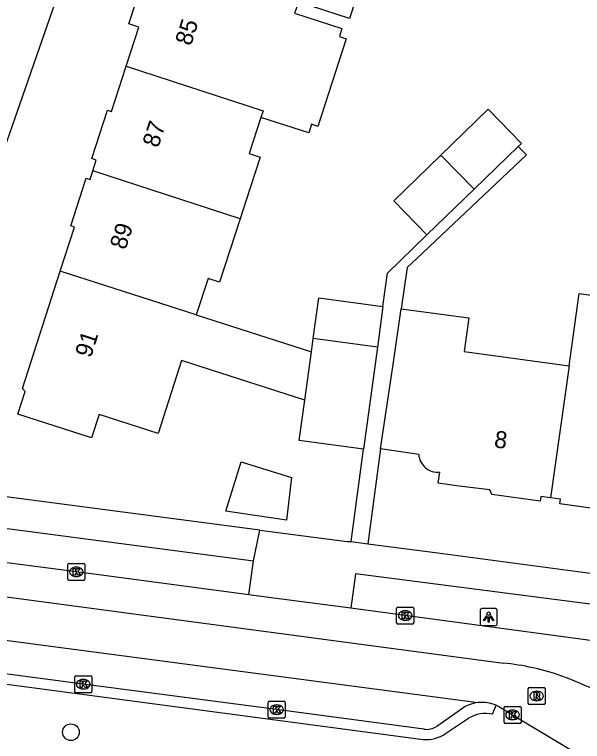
# Model space of a CAD drawing. Extents: x 161402 to 161933, y 381650 to 382313.
# Drawn here: x 161760.54 to 161793.88, y 381673.98 to 381716.7 of the extents above; entities that cross this region are included whole.
import ezdxf

# ---------------------------------------------------------------- set-up
doc = ezdxf.new("R2010")
doc.units = 0
for name, color, linetype in [('IMGEO_Boom', 7, 'Continuous'), ('IMGEO_Kolk', 7, 'Continuous'), ('IMGEO_Lichtpunt', 7, 'Continuous'), ('IMGEO_Pand', 7, 'Continuous'), ('IMGEO_Pand_nummerreeks', 7, 'Continuous'), ('IMGEO_Pand_vergunning_verleend', 7, 'Continuous'), ('IMGEO_Rijbaan_lokaal_gesloten', 7, 'Continuous'), ('IMGEO_Rijbaan_lokaal_open', 7, 'Continuous'), ('IMGEO_Rioolput', 7, 'Continuous'), ('IMGEO_Voetpad_open', 7, 'Continuous')]:
    doc.layers.add(name, color=color, linetype=linetype)

msp = doc.modelspace()

# ---------------------------------------------------------------- linework, layer by layer
at = {"layer": 'IMGEO_Boom'}
msp.add_circle((161763.852, 381674.528), 0.489, dxfattribs=at)
at = {"layer": 'IMGEO_Kolk'}
for p, q in [((161763.669, 381683.525), (161763.669, 381684.377)), ((161763.744, 381684.451), (161764.596, 381684.451)), ((161764.157, 381684.231), (161764.182, 381684.231)), ((161764.67, 381684.377), (161764.67, 381683.525)), ((161764.596, 381683.451), (161763.744, 381683.451)), ((161764.18, 381683.671), (161764.155, 381683.671)), ((161782.973, 381680.957), (161782.973, 381681.809)), ((161783.048, 381681.883), (161783.9, 381681.883)), ((161783.461, 381681.663), (161783.486, 381681.663)), ((161783.974, 381681.809), (161783.974, 381680.957)), ((161783.9, 381680.883), (161783.048, 381680.883)), ((161783.484, 381681.103), (161783.459, 381681.103)), ((161764.148, 381677.847), (161765, 381677.847)), ((161764.073, 381676.921), (161764.073, 381677.773)), ((161764.561, 381677.627), (161764.586, 381677.627)), ((161765.074, 381677.773), (161765.074, 381676.921)), ((161764.584, 381677.067), (161764.559, 381677.067)), ((161765, 381676.847), (161764.148, 381676.847)), ((161775.427, 381675.427), (161775.427, 381676.279)), ((161775.502, 381676.353), (161776.354, 381676.353)), ((161775.915, 381676.133), (161775.94, 381676.133)), ((161776.428, 381676.279), (161776.428, 381675.427)), ((161789.279, 381675.118), (161789.279, 381675.97)), ((161789.354, 381676.044), (161790.206, 381676.044)), ((161789.767, 381675.824), (161789.792, 381675.824)), ((161790.28, 381675.97), (161790.28, 381675.118)), ((161776.354, 381675.353), (161775.502, 381675.353)), ((161775.938, 381675.573), (161775.913, 381675.573)), ((161789.79, 381675.264), (161789.765, 381675.264)), ((161790.206, 381675.044), (161789.354, 381675.044))]:
    msp.add_line(p, q, dxfattribs=at)
for points in [[(161763.669, 381683.525), (161763.669, 381684.377)], [(161763.744, 381684.451), (161764.596, 381684.451)], [(161764.67, 381684.377), (161764.67, 381683.525)], [(161763.99, 381684.151), (161764.113, 381684.151), (161764.113, 381684), (161764.243, 381684.151), (161764.407, 381684.151), (161764.261, 381684), (161764.414, 381683.751), (161764.262, 381683.751), (161764.177, 381683.915), (161764.113, 381683.848), (161764.113, 381683.751), (161763.99, 381683.751), (161763.99, 381684.151)], [(161764.596, 381683.451), (161763.744, 381683.451)], [(161782.973, 381680.957), (161782.973, 381681.809)], [(161783.048, 381681.883), (161783.9, 381681.883)], [(161783.974, 381681.809), (161783.974, 381680.957)], [(161783.294, 381681.583), (161783.417, 381681.583), (161783.417, 381681.432), (161783.547, 381681.583), (161783.711, 381681.583), (161783.565, 381681.432), (161783.718, 381681.183), (161783.566, 381681.183), (161783.481, 381681.347), (161783.417, 381681.28), (161783.417, 381681.183), (161783.294, 381681.183), (161783.294, 381681.583)], [(161783.9, 381680.883), (161783.048, 381680.883)], [(161764.148, 381677.847), (161765, 381677.847)], [(161764.073, 381676.921), (161764.073, 381677.773)], [(161764.394, 381677.547), (161764.517, 381677.547), (161764.517, 381677.396), (161764.647, 381677.547), (161764.811, 381677.547), (161764.665, 381677.396), (161764.818, 381677.147), (161764.666, 381677.147), (161764.581, 381677.311), (161764.517, 381677.244), (161764.517, 381677.147), (161764.394, 381677.147), (161764.394, 381677.547)], [(161765.074, 381677.773), (161765.074, 381676.921)], [(161765, 381676.847), (161764.148, 381676.847)], [(161775.427, 381675.427), (161775.427, 381676.279)], [(161775.502, 381676.353), (161776.354, 381676.353)], [(161776.428, 381676.279), (161776.428, 381675.427)], [(161775.748, 381676.053), (161775.871, 381676.053), (161775.871, 381675.902), (161776.001, 381676.053), (161776.165, 381676.053), (161776.019, 381675.902), (161776.172, 381675.653), (161776.02, 381675.653), (161775.935, 381675.817), (161775.871, 381675.75), (161775.871, 381675.653), (161775.748, 381675.653), (161775.748, 381676.053)], [(161789.279, 381675.118), (161789.279, 381675.97)], [(161789.354, 381676.044), (161790.206, 381676.044)], [(161789.6, 381675.744), (161789.723, 381675.744), (161789.723, 381675.593), (161789.853, 381675.744), (161790.017, 381675.744), (161789.871, 381675.593), (161790.024, 381675.344), (161789.872, 381675.344), (161789.787, 381675.508), (161789.723, 381675.441), (161789.723, 381675.344), (161789.6, 381675.344), (161789.6, 381675.744)], [(161790.28, 381675.97), (161790.28, 381675.118)], [(161776.354, 381675.353), (161775.502, 381675.353)], [(161790.206, 381675.044), (161789.354, 381675.044)]]:
    msp.add_lwpolyline(points, dxfattribs=at)
for centre, start, end in [((161763.746, 381684.375), 91.552, 178.448), ((161763.746, 381684.375), 91.552, 178.448), ((161764.594, 381684.375), 1.552, 88.448), ((161764.594, 381684.375), 1.552, 88.448), ((161763.746, 381683.527), 181.552, 268.448), ((161763.746, 381683.527), 181.552, 268.448), ((161764.594, 381683.527), 271.552, 358.448), ((161764.594, 381683.527), 271.552, 358.448), ((161783.05, 381681.807), 91.552, 178.448), ((161783.05, 381681.807), 91.552, 178.448), ((161783.898, 381681.807), 1.552, 88.448), ((161783.898, 381681.807), 1.552, 88.448), ((161783.05, 381680.959), 181.552, 268.448), ((161783.05, 381680.959), 181.552, 268.448), ((161783.898, 381680.959), 271.552, 358.448), ((161783.898, 381680.959), 271.552, 358.448), ((161764.15, 381677.771), 91.552, 178.448), ((161764.15, 381677.771), 91.552, 178.448), ((161764.998, 381677.771), 1.552, 88.448), ((161764.998, 381677.771), 1.552, 88.448), ((161764.15, 381676.923), 181.552, 268.448), ((161764.15, 381676.923), 181.552, 268.448), ((161764.998, 381676.923), 271.552, 358.448), ((161764.998, 381676.923), 271.552, 358.448), ((161775.504, 381676.277), 91.552, 178.448), ((161775.504, 381676.277), 91.552, 178.448), ((161776.352, 381676.277), 1.552, 88.448), ((161776.352, 381676.277), 1.552, 88.448), ((161789.356, 381675.968), 91.552, 178.448), ((161789.356, 381675.968), 91.552, 178.448), ((161790.204, 381675.968), 1.552, 88.448), ((161790.204, 381675.968), 1.552, 88.448), ((161775.504, 381675.429), 181.552, 268.448), ((161775.504, 381675.429), 181.552, 268.448), ((161776.352, 381675.429), 271.552, 358.448), ((161776.352, 381675.429), 271.552, 358.448), ((161789.356, 381675.12), 181.552, 268.448), ((161789.356, 381675.12), 181.552, 268.448), ((161790.204, 381675.12), 271.552, 358.448), ((161790.204, 381675.12), 271.552, 358.448)]:
    msp.add_arc(centre, 0.0765, start, end, dxfattribs=at)
for centre, major_axis, ratio, start_param, end_param in [((161764.156, 381683.951), (-0.387, 0.002), 0.722429, 4.712389, 7.853982), ((161764.181, 381683.951), (-0.39, 0.002), 0.717154, 1.570796, 4.712389), ((161783.46, 381681.383), (-0.387, 0.002), 0.722429, 4.712389, 7.853982), ((161783.485, 381681.383), (-0.39, 0.002), 0.717154, 1.570796, 4.712389), ((161764.56, 381677.347), (-0.387, 0.002), 0.722429, 4.712389, 7.853982), ((161764.585, 381677.347), (-0.39, 0.002), 0.717154, 1.570796, 4.712389), ((161775.914, 381675.853), (-0.387, 0.002), 0.722429, 4.712389, 7.853982), ((161775.939, 381675.853), (-0.39, 0.002), 0.717154, 1.570796, 4.712389), ((161789.766, 381675.544), (-0.387, 0.002), 0.722429, 4.712389, 7.853982), ((161789.791, 381675.544), (-0.39, 0.002), 0.717154, 1.570796, 4.712389)]:
    msp.add_ellipse(centre, major_axis=major_axis, ratio=ratio, start_param=start_param, end_param=end_param, dxfattribs=at)
at = {"layer": 'IMGEO_Lichtpunt'}
for p, q in [((161787.877, 381681.695), (161787.877, 381680.888)), ((161787.877, 381681.695), (161787.877, 381680.888)), ((161788.779, 381681.79), (161787.971, 381681.79)), ((161788.779, 381681.79), (161787.971, 381681.79)), ((161788.873, 381680.888), (161788.873, 381681.695)), ((161788.873, 381680.888), (161788.873, 381681.695)), ((161787.971, 381680.794), (161788.779, 381680.794)), ((161787.971, 381680.794), (161788.779, 381680.794))]:
    msp.add_line(p, q, dxfattribs=at)
for points in [[(161788.251, 381681.359), (161788.29, 381681.331), (161788.102, 381681.069), (161788.064, 381681.096), (161788.251, 381681.359)], [(161788.353, 381681.311), (161788.4, 381681.311), (161788.4, 381680.989), (161788.353, 381680.989), (161788.353, 381681.311)], [(161788.463, 381681.331), (161788.501, 381681.358), (161788.688, 381681.096), (161788.649, 381681.068), (161788.463, 381681.331)]]:
    msp.add_lwpolyline(points, dxfattribs=at)
msp.add_circle((161788.376, 381681.493), 0.0994, dxfattribs=at)
for centre, start, end in [((161787.971, 381681.695), 90, 180), ((161787.971, 381681.695), 90, 180), ((161788.779, 381681.695), 0, 90), ((161788.779, 381681.695), 0, 90), ((161787.971, 381680.888), 180, 270), ((161787.971, 381680.888), 180, 270), ((161788.779, 381680.888), 270, 0), ((161788.779, 381680.888), 270, 360)]:
    msp.add_arc(centre, 0.0946, start, end, dxfattribs=at)
at = {"layer": 'IMGEO_Pand'}
for points in [[(161778.951, 381722.883), (161778.817, 381722.468), (161781.826, 381721.497), (161780.266, 381716.653), (161780.21, 381716.479), (161777.199, 381717.451), (161777.065, 381717.036)], [(161767.099, 381713.662), (161767.841, 381715.963), (161767.254, 381716.152), (161768.436, 381719.817)], [(161777.065, 381717.036), (161776.985, 381716.789), (161779.765, 381715.893), (161779.609, 381715.41), (161780.015, 381715.279), (161778.354, 381710.13), (161777.971, 381710.254), (161777.809, 381709.753), (161775.008, 381710.656)], [(161765.14, 381707.52), (161765.342, 381708.149), (161765.079, 381708.234), (161765.998, 381711.084), (161766.242, 381711.005), (161767.099, 381713.662)], [(161767.099, 381713.662), (161775.131, 381711.038), (161775.008, 381710.656)], [(161785.523, 381708.399), (161788.343, 381711.135), (161790.298, 381709.126), (161790.111, 381708.944)], [(161775.008, 381710.656), (161774.323, 381708.534), (161774.952, 381708.33), (161774.117, 381705.74), (161773.781, 381704.698)], [(161790.111, 381708.944), (161787.523, 381706.434)], [(161784.755, 381703.749), (161782.801, 381705.758), (161785.523, 381708.399)], [(161785.523, 381708.399), (161785.622, 381708.375), (161787.523, 381706.434)], [(161763.227, 381701.624), (161764.064, 381704.217), (161763.836, 381704.29), (161764.739, 381707.088), (161764.976, 381707.012), (161765.14, 381707.52)], [(161773.781, 381704.698), (161765.14, 381707.52)], [(161787.523, 381706.434), (161784.755, 381703.749)], [(161773.781, 381704.698), (161772.582, 381700.981), (161771.905, 381701.199), (161771.213, 381699.052)], [(161777.583, 381694.042), (161770.348, 381696.372), (161768.967, 381692.089), (161765.514, 381693.203), (161765.068, 381691.819), (161760.733, 381693.217), (161761.162, 381694.548), (161761.002, 381694.725), (161763.227, 381701.624)], [(161771.213, 381699.052), (161763.227, 381701.624)], [(161778.075, 381697.672), (161778.399, 381700.063), (161782.171, 381699.551)], [(161793.095, 381696.061), (161793.69, 381700.304), (161799.95, 381699.426), (161799.359, 381695.212)], [(161782.171, 381699.551), (161781.847, 381697.16)], [(161782.028, 381691.189), (161782.773, 381696.134), (161783.242, 381699.406)], [(161783.242, 381699.406), (161787.203, 381698.874), (161786.935, 381696.897), (161793.095, 381696.061)], [(161771.213, 381699.052), (161777.967, 381696.877)], [(161777.967, 381696.877), (161778.075, 381697.672)], [(161781.847, 381697.16), (161778.075, 381697.672)], [(161781.847, 381697.16), (161781.032, 381691.152)], [(161777.583, 381694.042), (161777.967, 381696.877)], [(161793.095, 381696.061), (161792.005, 381688.294)], [(161781.032, 381691.152), (161777.26, 381691.663), (161777.583, 381694.042)], [(161784.271, 381690.852), (161782.028, 381691.189)], [(161792.005, 381688.294), (161791.432, 381688.372), (161791.396, 381688.106), (161788.552, 381688.492), (161788.44, 381688.767), (161786.652, 381688.992), (161785.408, 381689.17), (161785.5, 381689.813)], [(161798.265, 381687.412), (161795.543, 381687.782), (161795.51, 381687.543), (161792.563, 381687.942), (161792.6, 381688.213), (161792.005, 381688.294)]]:
    msp.add_lwpolyline(points, dxfattribs=at)
msp.add_arc((161785.386, 381690.925), 1.117, 183.729, 275.8484, dxfattribs=at)
at = {"layer": 'IMGEO_Pand_vergunning_verleend'}
msp.add_lwpolyline([(161772.951, 381687.518), (161773.841, 381690.415), (161776.797, 381689.505), (161776.509, 381686.983), (161772.951, 381687.518)], dxfattribs=at)
at = {"layer": 'IMGEO_Rijbaan_lokaal_gesloten'}
for points in [[(161774.303, 381682.604), (161764.17, 381683.951), (161758.113, 381684.736), (161755.889, 381685.036)], [(161755.649, 381683.069), (161789.238, 381678.584)], [(161780.28, 381681.817), (161775.305, 381682.472), (161774.303, 381682.604)], [(161797.978, 381679.434), (161783.474, 381681.383), (161780.28, 381681.817)]]:
    msp.add_lwpolyline(points, dxfattribs=at)
for centre, radius, start, end in [((161787.891, 381664.361), 14.287, 70.4853, 84.5882), ((161783.897, 381654.039), 25.352, 56.8562, 69.7711)]:
    msp.add_arc(centre, radius, start, end, dxfattribs=at)
at = {"layer": 'IMGEO_Rijbaan_lokaal_open'}
for points in [[(161755.812, 381680.487), (161787.753, 381676.267)], [(161788.825, 381676.108), (161789.016, 381676.015), (161789.78, 381675.544), (161800.409, 381669.174)]]:
    msp.add_lwpolyline(points, dxfattribs=at)
msp.add_arc((161787.995, 381674.208), 2.073, 66.4141, 96.7126, dxfattribs=at)
at = {"layer": 'IMGEO_Rioolput'}
for p, q in [((161790.694, 381676.229), (161790.694, 381677.081)), ((161790.769, 381677.155), (161791.621, 381677.155)), ((161791.182, 381676.935), (161791.207, 381676.935)), ((161791.695, 381677.081), (161791.695, 381676.229)), ((161791.621, 381676.155), (161790.769, 381676.155)), ((161791.205, 381676.375), (161791.18, 381676.375))]:
    msp.add_line(p, q, dxfattribs=at)
for points in [[(161790.694, 381676.229), (161790.694, 381677.081)], [(161790.769, 381677.155), (161791.621, 381677.155)], [(161791.695, 381677.081), (161791.695, 381676.229)], [(161791.283, 381676.853), (161791.031, 381676.855), (161791.031, 381676.455)], [(161791.031, 381676.455), (161791.155, 381676.455), (161791.155, 381676.617), (161791.166, 381676.617)], [(161791.209, 381676.774), (161791.155, 381676.774), (161791.155, 381676.693)], [(161791.155, 381676.693), (161791.207, 381676.693)], [(161791.213, 381676.588), (161791.284, 381676.455), (161791.424, 381676.455), (161791.359, 381676.581)], [(161791.621, 381676.155), (161790.769, 381676.155)]]:
    msp.add_lwpolyline(points, dxfattribs=at)
for centre, radius, start, end in [((161790.771, 381677.079), 0.0765, 91.552, 178.448), ((161790.771, 381677.079), 0.0765, 91.552, 178.448), ((161791.619, 381677.079), 0.0765, 1.552, 88.448), ((161791.619, 381677.079), 0.0765, 1.552, 88.448), ((161791.165, 381676.564), 0.0533, 26.0293, 88.6989), ((161791.191, 381676.882), 0.19, 274.7715, 282.9687), ((161791.215, 381676.678), 0.0964, 77.0061, 93.1865), ((161791.229, 381676.735), 0.0378, 276.6634, 79.6772), ((161791.282, 381676.743), 0.109, 350.3612, 89.416), ((161791.28, 381676.743), 0.112, 277.5842, 350.9817), ((161791.264, 381676.528), 0.108, 29.5134, 73.7905), ((161790.771, 381676.231), 0.0765, 181.552, 268.448), ((161790.771, 381676.231), 0.0765, 181.552, 268.448), ((161791.619, 381676.231), 0.0765, 271.552, 358.448), ((161791.619, 381676.231), 0.0765, 271.552, 358.448)]:
    msp.add_arc(centre, radius, start, end, dxfattribs=at)
for centre, major_axis, ratio, start_param, end_param in [((161791.181, 381676.655), (-0.387, 0.002), 0.722429, 4.712389, 7.853982), ((161791.206, 381676.655), (-0.39, 0.002), 0.717154, 1.570796, 4.712389)]:
    msp.add_ellipse(centre, major_axis=major_axis, ratio=ratio, start_param=start_param, end_param=end_param, dxfattribs=at)
at = {"layer": 'IMGEO_Voetpad_open'}
for points in [[(161774.933, 381686.404), (161758.095, 381688.61), (161755.465, 381688.954), (161753.951, 381692.163), (161755.462, 381695.988), (161767.515, 381730.653), (161773.48, 381750), (161778.317, 381767.408)], [(161790.111, 381708.944), (161790.59, 381708.45), (161784.155, 381702.376), (161783.591, 381701.843), (161783.242, 381699.406)], [(161782.171, 381699.551), (161782.435, 381701.499), (161784.755, 381703.749)], [(161780.312, 381685.735), (161781.032, 381691.152)], [(161782.028, 381691.189), (161781.286, 381685.605)], [(161754.178, 381685.267), (161754.441, 381687.245), (161774.573, 381684.604)], [(161774.573, 381684.604), (161774.933, 381686.404)], [(161774.933, 381686.404), (161780.075, 381685.73), (161780.312, 381685.735)], [(161780.312, 381685.735), (161781.286, 381685.605)], [(161781.286, 381685.605), (161785.387, 381685.06), (161810.335, 381681.743)], [(161774.303, 381682.604), (161774.573, 381684.604)], [(161816.794, 381676.903), (161817.073, 381679.111), (161780.562, 381683.829), (161780.28, 381681.817)], [(161784.575, 381674.706), (161775.928, 381675.853), (161764.574, 381677.347), (161755.55, 381678.541)], [(161755.36, 381677.968), (161784.529, 381674.098)], [(161788.602, 381675.587), (161788.825, 381676.108)], [(161786.863, 381675.949), (161785.325, 381674.864)], [(161785.846, 381674.444), (161787.201, 381675.354)]]:
    msp.add_lwpolyline(points, dxfattribs=at)
for centre, radius, start, end in [((161787.938, 381674.345), 1.93, 95.4929, 123.8311), ((161788.21, 381673.614), 2.012, 78.7738, 120.111), ((161784.732, 381675.821), 1.126, 262.0017, 301.791), ((161784.686, 381676.18), 2.088, 265.6855, 303.7546)]:
    msp.add_arc(centre, radius, start, end, dxfattribs=at)

# ---------------------------------------------------------------- texts
at = {"layer": 'IMGEO_Pand_nummerreeks'}
for s, rotation, p in [('85', 72.2557, (161770.894, 381714.82)), ('87', 72.2557, (161768.976, 381708.827)), ('89', 72.2542, (161767.058, 381702.834)), ('91', 72.1209, (161765.018, 381696.489)), ('8', 352.2841, (161788.659, 381691.273))]:
    msp.add_text(s, height=1, rotation=rotation, dxfattribs=at).set_placement(p)

doc.saveas('drawing.dxf')
